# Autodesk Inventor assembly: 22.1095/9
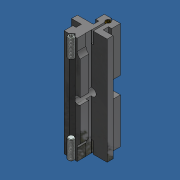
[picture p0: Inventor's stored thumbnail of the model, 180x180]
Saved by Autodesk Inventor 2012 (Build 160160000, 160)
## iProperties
Created: 2007-06
Part Number: 22.1095/9
Document SubType Name: Assembly
Designer: Andy Moles
Description: MACHINE TO 22.1095/9
Vendor: F
Stock Number: 22.1095
Mass: 38.2535 g
Surface Area: 149.165 cm^2
Volume: 35.3101 cm^3
Density: 1.08336 g/cm^3
Author: Andy Moles
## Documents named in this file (4)
- C:\Andys Backup Data\ANDY'S INVENTOR\INVENTOR LIBRARIES\PARTS LIBRARY\COMPONENTS LG\22.1095_9 SLIDE RAIL LN FOR SIDE LOCK.iam
- C:\Andys Backup Data\ANDY'S INVENTOR\INVENTOR LIBRARIES\PARTS LIBRARY\FASTENING ELEMENTS\SET SCREWS\21.1314 M4x8 SET SCREW POINTED.IPT
- C:\Andys Backup Data\ANDY'S INVENTOR\INVENTOR LIBRARIES\PARTS LIBRARY\COMPONENTS LG\SUBCOMPONENTS\22.1095_9 SLIDE RAIL LN FOR SIDE LOCK.ipt
- C:\Andys Backup Data\ANDY'S INVENTOR\INVENTOR LIBRARIES\PARTS LIBRARY\FASTENING ELEMENTS\SET SCREWS\21.1302 M5X16 SET SCREW FLAT.ipt
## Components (5 placed, 3 different names)
1. 22.1095_9 SLIDE RAIL LN FOR SIDE LOCK:1 — Insert:1, Insert:2, Flush:1, Mate:1, Mate:2, Flush:2
2. 21.1314 M4X8 SET SCREW CONE POINT DIN 914:1 — Insert:1
3. 21.1314 M4X8 SET SCREW CONE POINT DIN 914:2 — Insert:2
4. 21.1302 M5x16 Set Screw Flat Point DIN 913:1 — Flush:1, Mate:1, Mate:2, Mate:3
5. 21.1302 M5x16 Set Screw Flat Point DIN 913:2 — Flush:2, Mate:3
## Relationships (7: Mate 3, Insert 2, Flush 2)
- Insert:1: 22.1095_9 SLIDE RAIL LN FOR SIDE LOCK:1 ↔ 21.1314 M4X8 SET SCREW CONE POINT DIN 914:1
- Insert:2: 22.1095_9 SLIDE RAIL LN FOR SIDE LOCK:1 ↔ 21.1314 M4X8 SET SCREW CONE POINT DIN 914:2
- Flush:1: 22.1095_9 SLIDE RAIL LN FOR SIDE LOCK:1 ↔ 21.1302 M5x16 Set Screw Flat Point DIN 913:1
- Mate:1: 22.1095_9 SLIDE RAIL LN FOR SIDE LOCK:1 ↔ 21.1302 M5x16 Set Screw Flat Point DIN 913:1
- Mate:2: 22.1095_9 SLIDE RAIL LN FOR SIDE LOCK:1 ↔ 21.1302 M5x16 Set Screw Flat Point DIN 913:1
- Flush:2: 22.1095_9 SLIDE RAIL LN FOR SIDE LOCK:1 ↔ 21.1302 M5x16 Set Screw Flat Point DIN 913:2
- Mate:3: 21.1302 M5x16 Set Screw Flat Point DIN 913:1 ↔ 21.1302 M5x16 Set Screw Flat Point DIN 913:2
